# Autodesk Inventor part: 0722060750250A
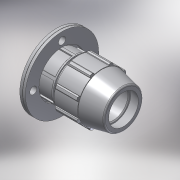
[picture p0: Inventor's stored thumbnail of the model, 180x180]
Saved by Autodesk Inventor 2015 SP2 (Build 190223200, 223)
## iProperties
Created: 2017-02
Part Number: 0722060750250A
Material: PVC-Piping
Description: PLASSON COMPRESSION FLANGE ADAPTOR 75-2.1/2"
Document SubType Name: Modeling
Designer: KIM
Mass: 92.6774 g
Surface Area: 199.44 cm^2
Volume: 66.1981 cm^3
Density: 1.4 g/cm^3
Appearance: Smooth - White
Author: KIM
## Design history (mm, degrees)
derived "87220.ipt"
feature "Solid1::87220.ipt"
tag "TaggingFeature1"
body "Solid1"
other parameters: "d2" = 75, "d4" = 23.42857, "d5" = 52.48, "d7" = 134, "d9" = 23.42857, "d11" = 4.68571, "d12" = 107.2, "d13" = 120 deg, "d14" = 97.5, "d15" = 12 deg, "d18" = 3.75, "d19" = 35 deg, "d20" = 17.5 deg, "d21" = 124.62, "d23" = 0, "d25" = 360 deg, "d27" = 2.68, "d34" = 6.7, "d36" = 0, "d42" = 57.4, "d43" = 4.02, "d46" = 2.25, "d53" = 1.5, "d55" = 360 deg, "d70" = 164, "d71" = 185, "d72" = 65, "d73" = 13.66667, "d74" = 90 deg, "d75" = 0.3, "d76" = 185, "d77" = 18, "d78" = 72.5, "d80" = 0, "d82" = 360 deg, "d85" = 113.9, "d86" = 107.2, "d87" = 2.3125, "d88" = 0.3, "d93" = 8.2, "d94" = 152, "d95" = 65, "d_" = 75, "E_" = 134, "H_" = 164, "l_" = 152, "D_" = 185, "Dp_" = 145, "S_" = 18, "DN_" = 65
